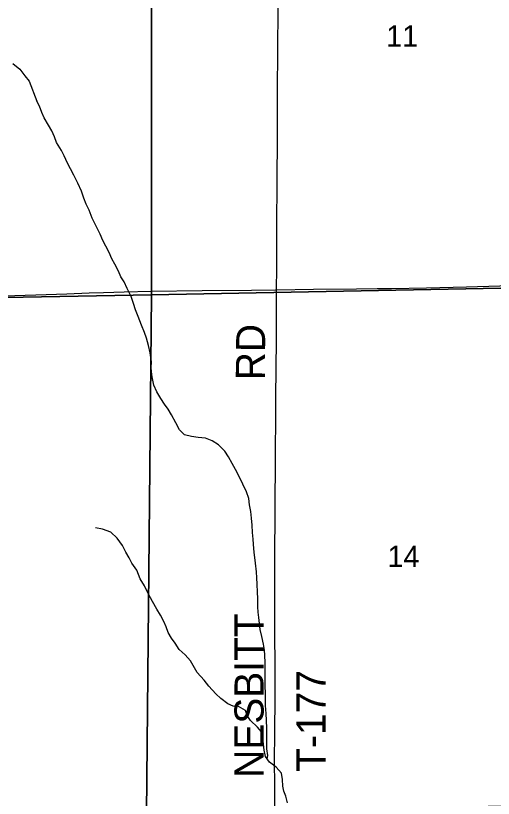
# Model space of a CAD drawing. Extents: x 0 to 45.9, y 0 to 22.
# Drawn here: x 3.224 to 4.156, y 16.732 to 18.26 of the extents above; entities that cross this region are included whole.
import ezdxf

# ---------------------------------------------------------------- set-up
doc = ezdxf.new("R2010")
doc.units = 0
for name, color, linetype in [('GM_X_County_Road', 7, 'Continuous'), ('GM_X_Minor_River', 7, 'Continuous'), ('GM_X_Section', 7, 'Continuous'), ('GM_X_Section_Text', 7, 'Continuous'), ('GM_X_Township_Road', 7, 'Continuous'), ('GM_X_Township_Road_Text', 7, 'Continuous')]:
    doc.layers.add(name, color=color, linetype=linetype)

msp = doc.modelspace()

# ---------------------------------------------------------------- linework, layer by layer
at = {"layer": 'GM_X_County_Road'}
for points in [[(2.9855, 17.7066), (3.0443, 17.7085), (3.181, 17.7124), (3.3238, 17.7169), (3.3673, 17.7184), (3.3952, 17.7193), (3.4356, 17.7205), (3.4884, 17.7219), (3.5878, 17.7234), (3.6842, 17.7241), (3.7307, 17.7247), (3.7332, 17.7248)], [(3.7332, 17.7248), (3.8053, 17.7259), (3.8892, 17.7267), (3.9296, 17.7269), (3.9575, 17.7274), (4.0259, 17.7287), (4.1035, 17.7305), (4.1687, 17.7325), (4.2153, 17.7335), (4.262, 17.7342), (4.2744, 17.734), (4.2807, 17.7336), (4.2869, 17.7327), (4.29, 17.732), (4.293, 17.7312), (4.2989, 17.7289), (4.3046, 17.7261), (4.3207, 17.7167), (4.327, 17.7129)]]:
    msp.add_lwpolyline(points, dxfattribs=at)
at = {"layer": 'GM_X_Minor_River'}
for points in [[(3.2184, 18.1662), (3.2322, 18.155), (3.2419, 18.142), (3.2504, 18.1317), (3.2652, 18.0929)], [(3.715, 16.8089), (3.7161, 16.8159), (3.714, 16.8285), (3.7143, 16.8524), (3.7138, 16.8691), (3.7132, 16.8839), (3.7127, 16.8979), (3.7117, 16.9131), (3.7113, 16.9359), (3.7108, 16.9522), (3.7111, 16.9753), (3.7105, 16.9875), (3.7106, 16.9969), (3.7104, 17.0117), (3.7094, 17.0212), (3.7073, 17.0327), (3.7045, 17.0482), (3.7012, 17.0619), (3.6999, 17.0733), (3.6981, 17.0851), (3.6971, 17.0954), (3.6965, 17.106), (3.6964, 17.1223), (3.6958, 17.1345), (3.6952, 17.15), (3.6946, 17.1626), (3.6937, 17.174), (3.6916, 17.1911), (3.6906, 17.2021), (3.6896, 17.212), (3.6879, 17.2283), (3.6873, 17.2378), (3.6863, 17.2507), (3.6854, 17.2655), (3.6841, 17.2792), (3.6827, 17.2917), (3.6803, 17.305), (3.6789, 17.3176), (3.6742, 17.3305), (3.6671, 17.3454), (3.6594, 17.3615), (3.6527, 17.3737), (3.6464, 17.3859), (3.6394, 17.3985), (3.6323, 17.4096), (3.62, 17.4219), (3.6072, 17.4301), (3.594, 17.4348), (3.5803, 17.4365), (3.5667, 17.4386), (3.5535, 17.4414), (3.5434, 17.4514), (3.5363, 17.4652), (3.5282, 17.4805), (3.5215, 17.4915), (3.5145, 17.5015), (3.5074, 17.5126), (3.4996, 17.5256), (3.4937, 17.5382), (3.4916, 17.5481), (3.4898, 17.5587), (3.4885, 17.5724), (3.4886, 17.5838), (3.4862, 17.6013), (3.483, 17.6157), (3.4794, 17.6302), (3.475, 17.6416), (3.4695, 17.6558), (3.4629, 17.6725), (3.4578, 17.6855), (3.4538, 17.6981), (3.449, 17.7114), (3.4416, 17.7271), (3.4357, 17.7404), (3.429, 17.75), (3.4242, 17.7607), (3.4172, 17.7744), (3.4117, 17.7848), (3.4062, 17.7974), (3.3999, 17.81), (3.394, 17.821), (3.3884, 17.8333), (3.3733, 17.8646), (3.3674, 17.8802), (3.3615, 17.8917), (3.3568, 17.9035), (3.352, 17.9172), (3.345, 17.9325), (3.3372, 17.9481), (3.3306, 17.9604), (3.325, 17.9718), (3.3184, 17.986), (3.3132, 17.9963), (3.3036, 18.012), (3.2996, 18.023), (3.2944, 18.0348), (3.2877, 18.0459), (3.2796, 18.0601), (3.2748, 18.0708), (3.27, 18.0833), (3.2652, 18.0929)], [(3.7543, 16.7236), (3.7511, 16.7362), (3.7474, 16.7461), (3.7453, 16.756), (3.7443, 16.7689), (3.7426, 16.7814), (3.7321, 16.7929), (3.7194, 16.803), (3.7115, 16.8137), (3.709, 16.8259), (3.7073, 16.8377), (3.7063, 16.8494), (3.7035, 16.8616), (3.696, 16.8712), (3.6821, 16.8839), (3.6758, 16.8938), (3.6721, 16.9034), (3.6586, 16.9112), (3.648, 16.9117), (3.6378, 16.9164), (3.6243, 16.9272), (3.6145, 16.936), (3.6011, 16.951), (3.5914, 16.9625), (3.5783, 16.9775), (3.5649, 17.0004), (3.5545, 17.0119), (3.5432, 17.0223), (3.5351, 17.035), (3.528, 17.0449), (3.5217, 17.0556), (3.5177, 17.0671), (3.5129, 17.077), (3.5066, 17.0896), (3.4992, 17.1011), (3.4906, 17.1164), (3.4829, 17.1305), (3.4755, 17.1469), (3.4666, 17.1607), (3.4603, 17.1775), (3.4507, 17.1909), (3.4451, 17.2012), (3.4388, 17.2127), (3.4325, 17.2257), (3.4221, 17.2398), (3.4094, 17.2514), (3.3931, 17.2577), (3.3795, 17.2601)]]:
    msp.add_lwpolyline(points, dxfattribs=at)
at = {"layer": 'GM_X_Section'}
for points in [[(3.4889, 18.7329), (4.4658, 18.7509), (4.477, 17.7336), (3.4888, 17.7149)], [(2.5019, 18.7014), (3.4889, 18.7329), (3.4888, 17.7149), (2.4867, 17.6967)], [(3.4888, 17.7149), (4.477, 17.7336), (4.4801, 16.7228), (3.479, 16.7029)], [(2.4867, 17.6967), (3.4888, 17.7149), (3.479, 16.7029), (2.4763, 16.6833)]]:
    msp.add_lwpolyline(points, close=True, dxfattribs=at)
at = {"layer": 'GM_X_Township_Road'}
for points in [[(3.7332, 17.7248), (3.7332, 17.7307), (3.7333, 17.7618), (3.7337, 17.8332), (3.7336, 17.8674), (3.7341, 17.9171), (3.7343, 17.9575), (3.7346, 18.001), (3.7349, 18.0539), (3.7346, 18.0818), (3.7351, 18.116), (3.7357, 18.1875), (3.7364, 18.2776), (3.7371, 18.3428), (3.7378, 18.4951), (3.7383, 18.5666), (3.7383, 18.6068), (3.7381, 18.6207), (3.7382, 18.6245), (3.7383, 18.6283), (3.7386, 18.6319)], [(3.7293, 16.7137), (3.7294, 16.7209), (3.7294, 16.724), (3.7294, 16.7613), (3.7293, 16.8016), (3.7299, 16.8638), (3.7302, 16.9259), (3.7302, 16.9974), (3.7299, 17.0471), (3.7297, 17.0875), (3.7299, 17.1279), (3.7299, 17.1714), (3.7296, 17.2087), (3.7298, 17.2304), (3.7301, 17.2646), (3.7305, 17.3205), (3.7309, 17.3734), (3.7319, 17.5101), (3.7325, 17.5753), (3.7326, 17.6219), (3.7331, 17.6717), (3.733, 17.6996), (3.7332, 17.7248)]]:
    msp.add_lwpolyline(points, dxfattribs=at)

# ---------------------------------------------------------------- texts
at = {"layer": 'GM_X_Section_Text'}
for s, p in [('11', (3.9471, 18.1989)), ('14', (3.9496, 17.1834))]:
    msp.add_text(s, height=0.04186, rotation=0, dxfattribs=at).set_placement(p)
at = {"layer": 'GM_X_Township_Road_Text'}
for s, rotation, p in [('RD', 89.5068, (3.7102, 17.5479)), ('NESBITT', 90, (3.7077, 16.7722)), ('T-177', 90, (3.8287, 16.7839))]:
    msp.add_text(s, height=0.05682, rotation=rotation, dxfattribs=at).set_placement(p)

doc.saveas('drawing.dxf')
